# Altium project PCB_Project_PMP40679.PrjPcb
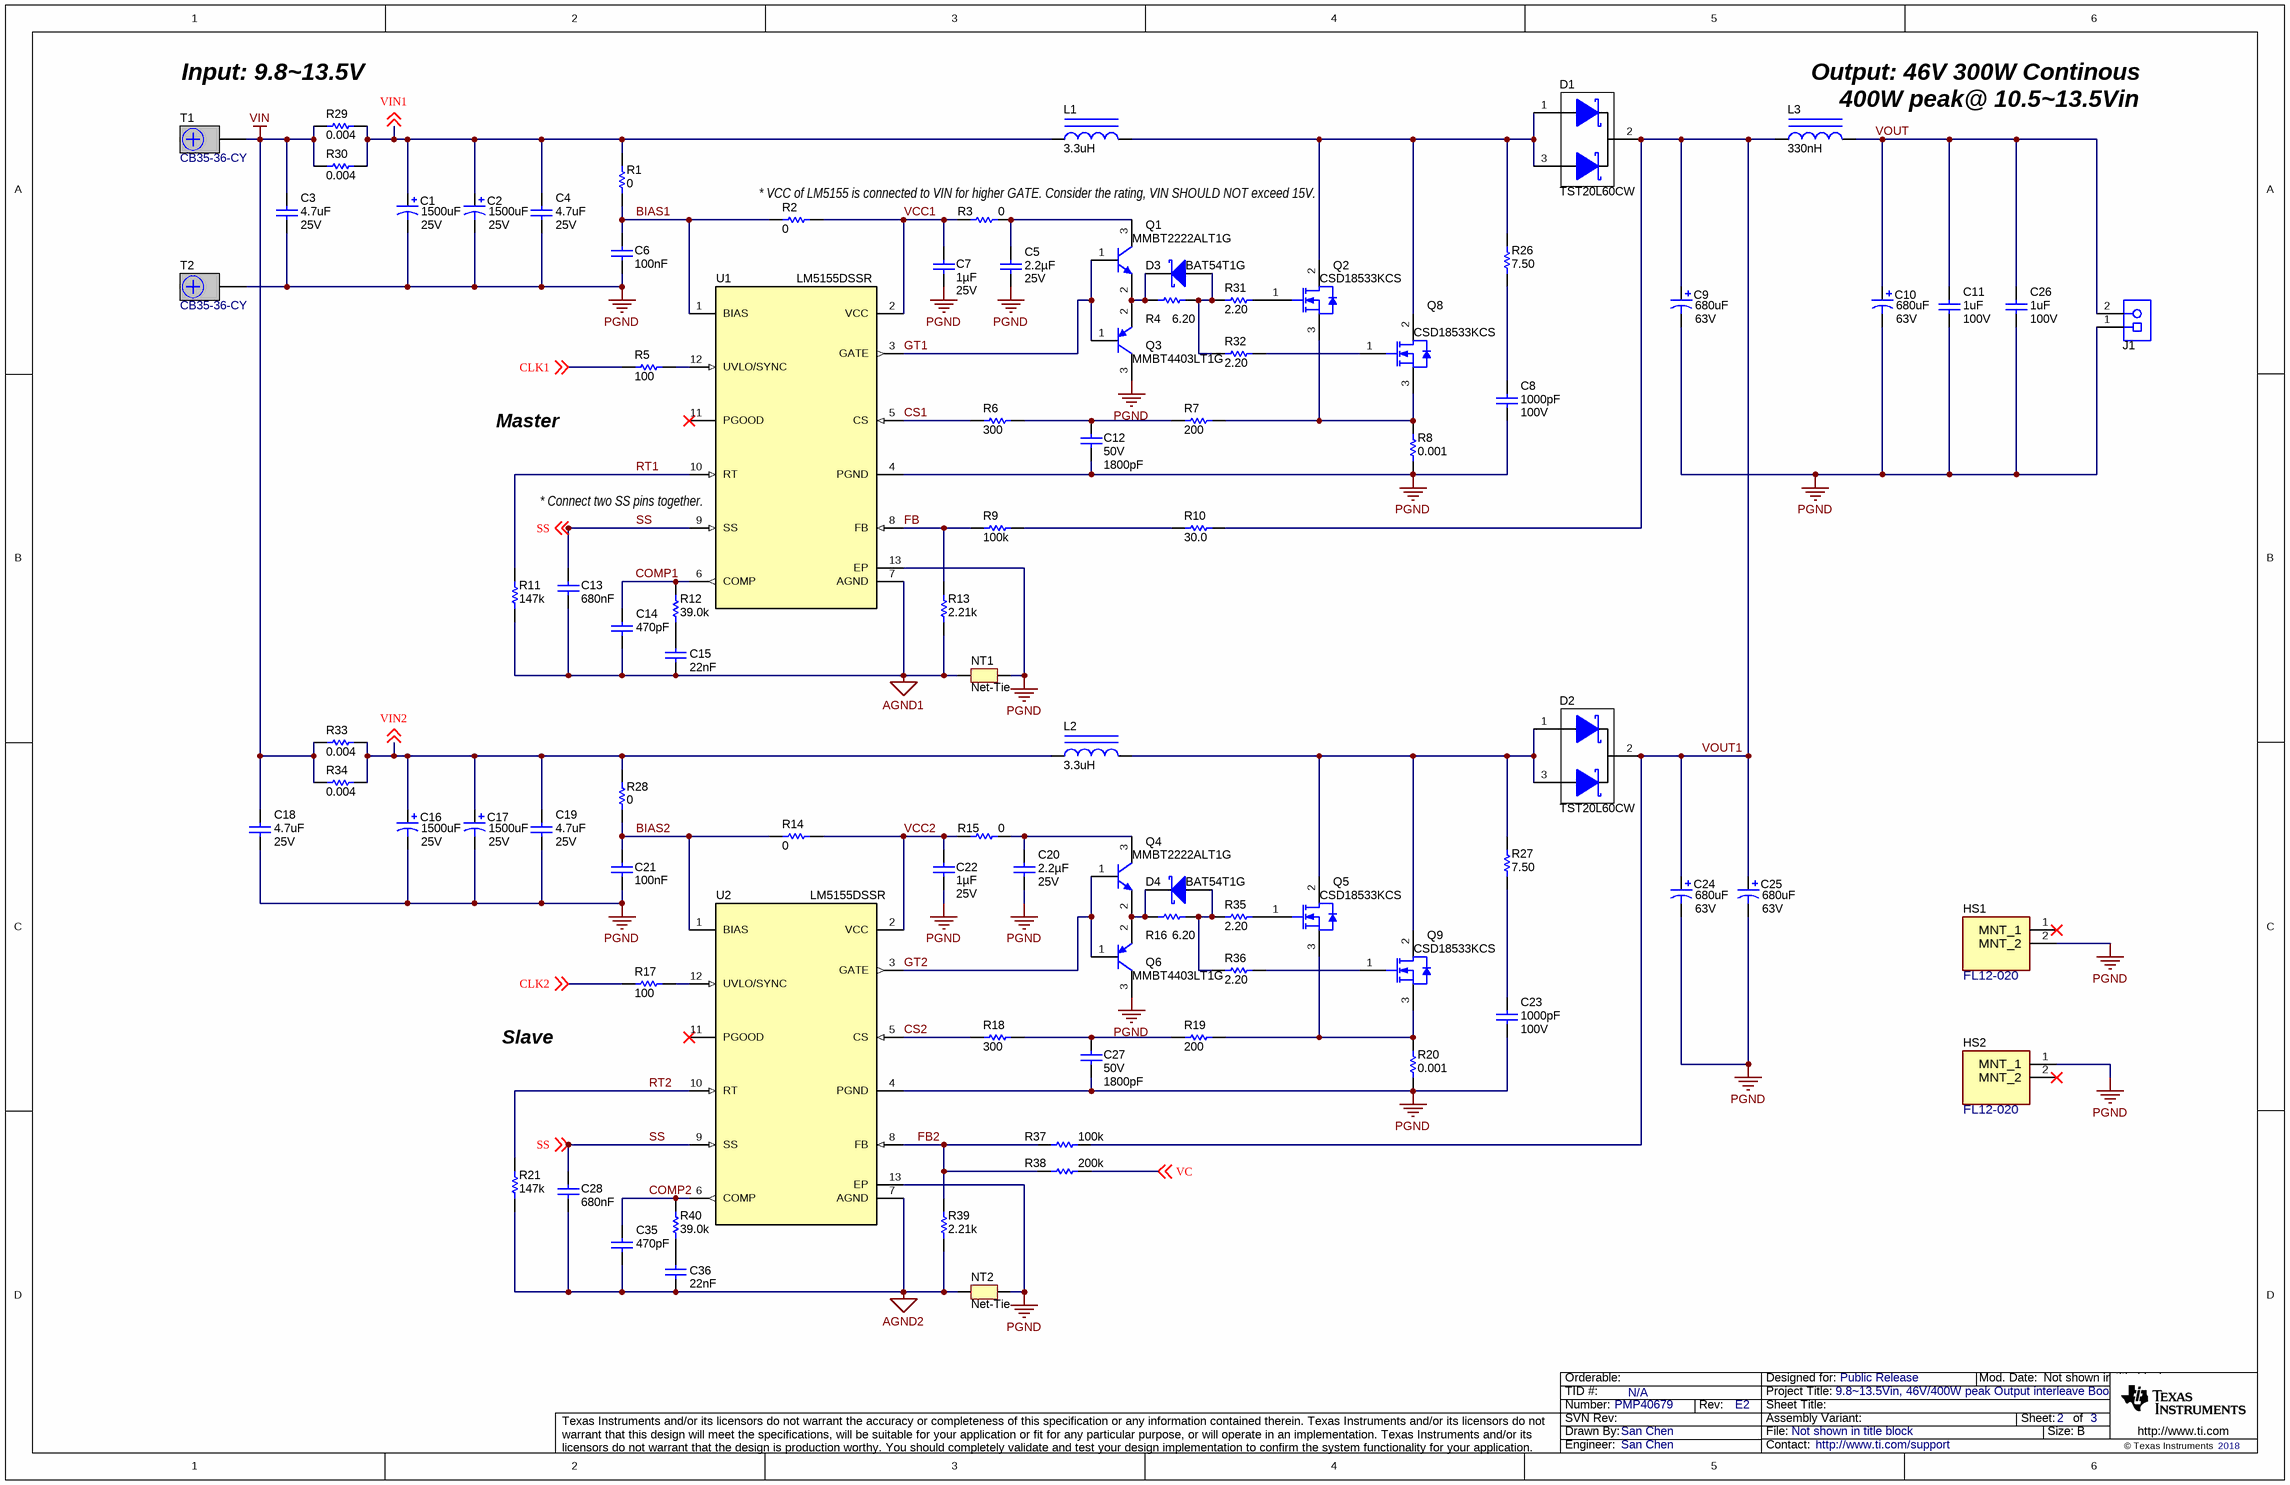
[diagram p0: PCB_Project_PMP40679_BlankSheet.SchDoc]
CopyrightYear: 2018; PCB_Layout: San Chen; PCB_Rev: E2; PRJ_Customer: Public Release; PRJ_Engineer: San Chen; PRJ_Number: PMP40679; PRJ_Title: 9.8~13.5Vin, 46V/400W peak Output interleave Boost; SCH_Rev: E2; TechSupport: http://www.ti.com/support; TID: N/A
3 sheets, 114 parts. Net scope: global (net labels, ports and power ports of the same name join across sheets).
Board file: PCB_Project_PMP40679_PCB.PcbDoc
Sheets:
  PCB_Project_PMP40679_BlankSheet.SchDoc
  PCB_Project_PMP40679_CoverSheet.SchDoc
  PCB_Project_PMP40679_EVM_Hardware.SchDoc

## Sheet PCB_Project_PMP40679_BlankSheet.SchDoc
size 431 x 279 mm; Date: Not shown in title block; ApprovedBy: Not shown in title block; CheckedBy: Not shown in title block; Author: Not shown in title block; CompanyName: Not shown in title block; DrawnBy: San Chen; Engineer: Not shown in title block; Organization: Not shown in title block; Address1: Not shown in title block; Address2: Not shown in title block; Address3: Not shown in title block; Address4: Not shown in title block; DocumentNumber: 1; Revision: Use project parameter SCH_Rev; SheetNumber: 2; SheetTotal: 3; PageSetup: Record=PageOptions¦CenterHorizontal=True¦CenterVertical=True¦PrintScale=1.00¦XCorrection=1.00¦YCorrection=1.00¦PrintKind=0¦BorderSize=5000000¦LeftOffset=0¦BottomOffset=0¦Orientation=2¦PaperLength=1000¦PaperWidth=1000¦Scale=100¦PaperSource=15¦PrintQuality=600¦MediaType=1¦DitherType=10¦PaperKind=Letter¦PrintScaleMode=1

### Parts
C1  VDC_V: 25V  ValueDisplayed: 1500uF  [Chemi-Con_1250x2500]  (hidden comment: EKY-250ELL152MK25S)
C2  VDC_V: 25V  ValueDisplayed: 1500uF  [Chemi-Con_1250x2500]  (hidden comment: EKY-250ELL152MK25S)
C3  VDC_V: 25V  ValueDisplayed: 4.7uF  [1206L]  (hidden comment: C3216X7R1E475K085AB)
C4  VDC_V: 25V  ValueDisplayed: 4.7uF  [1206L]  (hidden comment: C3216X7R1E475K085AB)
C5  Cap_F: 2.2µF  VDC_V: 25V  [0805_150]  (hidden comment: 08053C225KAT2A)
C6  Cap_F: 100nF  [0603]  (hidden comment: C0603C104K5RACTU)
C7  Cap_F: 1µF  VDC_V: 25V  [0603]  (hidden comment: C1608X7R1E105K080AB)
C8  VDC_V: 100V  ValueDisplayed: 1000pF  [0805_HV]  (hidden comment: GRM2165C2A102JA01D)
C9  VDC_V: 63V  ValueDisplayed: 680uF  [KY_1600x2500]  (hidden comment: EKY-630ELL681ML25S)
C10  VDC_V: 63V  ValueDisplayed: 680uF  [KY_1600x2500]  (hidden comment: EKY-630ELL681ML25S)
C11  VDC_V: 100V  ValueDisplayed: 1uF  [1206_180]  (hidden comment: C3216X7R2A105K160AA)
C12  VDC_V: 50V  ValueDisplayed: 1800pF  [0603]  (hidden comment: GRM1885C1H182JA01D)
C13  Cap_F: 680nF  [0603]  (hidden comment: GRM188R71A684KA61D)
C14  ValueDisplayed: 470pF  [0603]  (hidden comment: GRM1885C1H471JA01D)
C15  Cap_F: 22nF  [0603]  (hidden comment: C0603C223K3RACTU)
C16  VDC_V: 25V  ValueDisplayed: 1500uF  [Chemi-Con_1250x2500]  (hidden comment: EKY-250ELL152MK25S)
C17  VDC_V: 25V  ValueDisplayed: 1500uF  [Chemi-Con_1250x2500]  (hidden comment: EKY-250ELL152MK25S)
C18  VDC_V: 25V  ValueDisplayed: 4.7uF  [1206L]  (hidden comment: C3216X7R1E475K085AB)
C19  VDC_V: 25V  ValueDisplayed: 4.7uF  [1206L]  (hidden comment: C3216X7R1E475K085AB)
C20  Cap_F: 2.2µF  VDC_V: 25V  [0805_150]  (hidden comment: 08053C225KAT2A)
C21  Cap_F: 100nF  [0603]  (hidden comment: C0603C104K5RACTU)
C22  Cap_F: 1µF  VDC_V: 25V  [0603]  (hidden comment: C1608X7R1E105K080AB)
C23  VDC_V: 100V  ValueDisplayed: 1000pF  [0805_HV]  (hidden comment: GRM2165C2A102JA01D)
C24  VDC_V: 63V  ValueDisplayed: 680uF  [KY_1600x2500]  (hidden comment: EKY-630ELL681ML25S)
C25  VDC_V: 63V  ValueDisplayed: 680uF  [KY_1600x2500]  (hidden comment: EKY-630ELL681ML25S)
C26  VDC_V: 100V  ValueDisplayed: 1uF  [1206_180]  (hidden comment: C3216X7R2A105K160AA)
C27  VDC_V: 50V  ValueDisplayed: 1800pF  [0603]  (hidden comment: GRM1885C1H182JA01D)
C28  Cap_F: 680nF  [0603]  (hidden comment: GRM188R71A684KA61D)
C35  ValueDisplayed: 470pF  [0603]  (hidden comment: GRM1885C1H471JA01D)
C36  Cap_F: 22nF  [0603]  (hidden comment: C0603C223K3RACTU)
D1  TST20L60CW  [TO-220AB]
D2  TST20L60CW  [TO-220AB]
D3  BAT54T1G  [SOD-123]
D4  BAT54T1G  [SOD-123]
HS1  FL12-020  [PCBComponent_1]
HS2  FL12-020  [PCBComponent_1]
J1  1715721  [PhoenixContact_1715721]  (value not drawn)
L1  ValueDisplayed: 3.3uH  [SER2915L]  (hidden comment: SER2915L-332KL)
L2  ValueDisplayed: 3.3uH  [SER2915L]  (hidden comment: SER2915L-332KL)
L3  ValueDisplayed: 330nH  [WE-HCI_5040]  (hidden comment: 744316033)
NT1  Net-Tie  [Net-Tie_10mil]  (net tie, no BOM)
NT2  Net-Tie  [Net-Tie_10mil]  (net tie, no BOM)
Q1  MMBT2222ALT1G  [SOT-23]
Q2  CSD18533KCS  [KCS0003B]
Q3  MMBT4403LT1G  [SOT-23]
Q4  MMBT2222ALT1G  [SOT-23]
Q5  CSD18533KCS  [KCS0003B]
Q6  MMBT4403LT1G  [SOT-23]
Q8  CSD18533KCS  [KCS0003B]
Q9  CSD18533KCS  [KCS0003B]
R1  ValueDisplayed: 0  [0603]  (hidden comment: RC0603JR-070RL)
R2  ValueDisplayed: 0  [0603]  (hidden comment: RC0603JR-070RL)
R3  ValueDisplayed: 0  [0603]  (hidden comment: RC0603JR-070RL)
R4  ValueDisplayed: 6.20  [0805_HV]  (hidden comment: RC0805FR-076R2L)
R5  ValueDisplayed: 100  [0603]  (hidden comment: RC0603FR-07100RL)
R6  ValueDisplayed: 300  [0603]  (hidden comment: RC0603FR-07300RL)
R7  ValueDisplayed: 200  [0603]  (hidden comment: RC0603FR-07200RL)
R8  ValueDisplayed: 0.001  [2512]  (hidden comment: ERJ-M1WTF1M0U)
R9  ValueDisplayed: 100k  [0603]  (hidden comment: RC0603FR-07100KL)
R10  ValueDisplayed: 30.0  [0603]  (hidden comment: RC0603FR-0730RL)
R11  ValueDisplayed: 147k  [0603]  (hidden comment: RC0603FR-07147KL)
R12  ValueDisplayed: 39.0k  [0603]  (hidden comment: RC0603FR-0739KL)
R13  ValueDisplayed: 2.21k  [0603]  (hidden comment: RC0603FR-072K21L)
R14  ValueDisplayed: 0  [0603]  (hidden comment: RC0603JR-070RL)
R15  ValueDisplayed: 0  [0603]  (hidden comment: RC0603JR-070RL)
R16  ValueDisplayed: 6.20  [0805_HV]  (hidden comment: RC0805FR-076R2L)
R17  ValueDisplayed: 100  [0603]  (hidden comment: RC0603FR-07100RL)
R18  ValueDisplayed: 300  [0603]  (hidden comment: RC0603FR-07300RL)
R19  ValueDisplayed: 200  [0603]  (hidden comment: RC0603FR-07200RL)
R20  ValueDisplayed: 0.001  [2512]  (hidden comment: ERJ-M1WTF1M0U)
R21  ValueDisplayed: 147k  [0603]  (hidden comment: RC0603FR-07147KL)
R26  ValueDisplayed: 7.50  [2512]  (hidden comment: CRCW25127R50FKEG)
R27  ValueDisplayed: 7.50  [2512]  (hidden comment: CRCW25127R50FKEG)
R28  ValueDisplayed: 0  [0603]  (hidden comment: RC0603JR-070RL)
R29  ValueDisplayed: 0.004  [2512]  (hidden comment: ERJ-M1WTF4M0U)
R30  ValueDisplayed: 0.004  [2512]  (hidden comment: ERJ-M1WTF4M0U)
R31  ValueDisplayed: 2.20  [0805_HV]  (hidden comment: RC0805FR-072R2L)
R32  ValueDisplayed: 2.20  [0805_HV]  (hidden comment: RC0805FR-072R2L)
R33  ValueDisplayed: 0.004  [2512]  (hidden comment: ERJ-M1WTF4M0U)
R34  ValueDisplayed: 0.004  [2512]  (hidden comment: ERJ-M1WTF4M0U)
R35  ValueDisplayed: 2.20  [0805_HV]  (hidden comment: RC0805FR-072R2L)
R36  ValueDisplayed: 2.20  [0805_HV]  (hidden comment: RC0805FR-072R2L)
R37  ValueDisplayed: 100k  [0603]  (hidden comment: RC0603FR-07100KL)
R38  ValueDisplayed: 200k  [0603]  (hidden comment: RC0603FR-07200KL)
R39  ValueDisplayed: 2.21k  [0603]  (hidden comment: RC0603FR-072K21L)
R40  ValueDisplayed: 39.0k  [0603]  (hidden comment: RC0603FR-0739KL)
T1  CB35-36-CY  [CB35-36-CY]
T2  CB35-36-CY  [CB35-36-CY]
U1  LM5155DSSR  [DSS0012B]
U2  LM5155DSSR  [DSS0012B]

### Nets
AGND1: C13.2 C14.2 C15.2 NT1.2 R11.1 R13.1 U1.7(AGND)
AGND2: C28.2 C35.2 C36.2 NT2.2 R21.1 R39.1 U2.7(AGND)
PGND: C1.2(-) C2.2(-) C3.2 C4.2 C5.2 C6.2 C7.2 C8.2 C9.2(-) C10.2(-) C11.2 C12.2 C16.2(-) C17.2(-) C18.2 C19.2 C20.2 C21.2 C22.2 C23.2 C24.2(-) C25.2(-) C26.2 C27.2 HS1.2(MNT_2) HS2.1(MNT_1) J1.1 NT1.1 NT2.1 Q3.3(C) Q6.3(C) R8.1 R20.1 T2.1 U1.4(PGND) U1.13(EP) U2.4(PGND) U2.13(EP)
VIN: C3.1 C18.1 R29.1 R30.1 R33.1 R34.1 T1.1
BIAS1: C6.1 R1.1 R2.2 U1.1(BIAS)
BIAS2: C21.1 R14.2 R28.1 U2.1(BIAS)
CLK1: R5.1 ; off-sheet CLK1
CLK2: R17.1 ; off-sheet CLK2
COMP1: C14.1 R12.2 U1.6(COMP)
COMP2: C35.1 R40.2 U2.6(COMP)
CS1: R6.1 U1.5(CS)
CS2: R18.1 U2.5(CS)
FB: R9.1 R13.2 U1.8(FB)
FB2: R37.1 R38.1 R39.2 U2.8(FB)
GT1: Q1.1(B) Q3.1(B) U1.3(GATE)
GT2: Q4.1(B) Q6.1(B) U2.3(GATE)
RT1: R11.2 U1.10(RT)
RT2: R21.2 U2.10(RT)
SS: C13.1 C28.1 U1.9(SS) U2.9(SS) ; off-sheet SS
VC: R38.2 ; off-sheet VC
VCC1: C7.1 R2.1 R3.2 U1.2(VCC)
VCC2: C22.1 R14.1 R15.2 U2.2(VCC)
VIN1: C1.1(+) C2.1(+) C4.1 L1.1 R1.2 R29.2 R30.2 ; off-sheet VIN1
VIN2: C16.1(+) C17.1(+) C19.1 L2.2 R28.2 R33.2 R34.2 ; off-sheet VIN2
VOUT: C10.1(+) C11.1 C26.1 J1.2 L3.2
VOUT1: C9.1(+) C24.1(+) C25.1(+) D1.2(K) D2.2(K) L3.1 R10.2 R37.2
NetC5_1: C5.1 Q1.3(C) R3.1
NetC8_1: C8.1 R26.1
NetC12_1: C12.1 R6.2 R7.1
NetC15_1: C15.1 R12.1
NetC20_1: C20.1 Q4.3(C) R15.1
NetC23_1: C23.1 R27.1
NetC27_1: C27.1 R18.2 R19.1
NetC36_1: C36.1 R40.1
NetD1_1: D1.1(A) D1.3(A) L1.2 Q2.2(D) Q8.2(D) R26.2
NetD2_1: D2.1(A) D2.3(A) L2.1 Q5.2(D) Q9.2(D) R27.2
NetD3_1: D3.1(K) Q1.2(E) Q3.2(E) R4.1
NetD3_2: D3.2(A) R4.2 R31.1 R32.1
NetD4_1: D4.1(K) Q4.2(E) Q6.2(E) R16.1
NetD4_2: D4.2(A) R16.2 R35.1 R36.1
NetQ2_1: Q2.1(G) R31.2
NetQ2_3: Q2.3(S) Q8.3(S) R7.2 R8.2
NetQ5_1: Q5.1(G) R35.2
NetQ5_3: Q5.3(S) Q9.3(S) R19.2 R20.2
NetQ8_1: Q8.1(G) R32.2
NetQ9_1: Q9.1(G) R36.2
NetR5_2: R5.2 U1.12(UVLO/SYNC)
NetR9_2: R9.2 R10.1
NetR17_2: R17.2 U2.12(UVLO/SYNC)

Not connected (* = marked no-connect by the designer): HS1 1(MNT_1)*; HS2 2(MNT_2)*; U1 11(PGOOD)*; U2 11(PGOOD)*

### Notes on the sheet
- Input: 9.8
  3.5V
- Output: 46V 300W Continous
- (near L3) 400W peak@ 10.5
  3.5Vin
- * VCC of LM5155 is connected to VIN for higher GATE. Consider the rating, VIN SHOULD NOT exceed 15V.
- Master
- (near U1) * Connect two SS pins together.
- Slave

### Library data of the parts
C1 C2 C16 C17 = CMP-0010401-1: CAP, AL, 1500 uF, 25 V, +/- 20%, TH; Manufacturer: Chemi-Con; TaMin_C: -40°C; Polarized: Y; SizeAreaWB_mm2: 210.25; Value1: Unknown; U/M: EA; Value: 1500uF; TaMax_C: 105°C; SizeZ_mm: 26.5; SizeX_mm: 12.5; Cap_Case: 12.5x25; SizeArea_mm2: 156.25; CompType: Capacitor; AEC Qualified: N; Cap_F: 1.5mF; IRMS_A: 2.23A; AEC Category: Q200
C3 C4 C18 C19 = CMP-0008693-2: CAP, CERM, 4.7 uF, 25 V, +/- 10%, X7R, 1206; Manufacturer: TDK; TaMin_C: -55°C; Polarized: N; SizeAreaWB_mm2: 10.92; Value1: Unknown; U/M: EA; Value: 4.7uF; TaMax_C: 125°C; SizeZ_mm: 1.35; SizeX_mm: 3.2; SizeY_mm: 1.6; Cap_Case: 1206; SizeArea_mm2: 5.12; CompType: Capacitor; Cap_F: 4.7µF; AEC Category: Q200
C5 C20 = CMP-0007573-2: CAP, CERM, 2.2 uF, 25 V, +/- 10%, X7R, 0805; Manufacturer: AVX; TaMin_C: -55°C; Polarized: N; SizeAreaWB_mm2: 6.75; Value1: Unknown; U/M: EA; Value: 2.2uF; TaMax_C: 125°C; SizeZ_mm: 1.5; SizeX_mm: 2; SizeY_mm: 1.25; Cap_Case: 0805; SizeArea_mm2: 2.5; AEC Category: Q200
C6 C21 = CMP-0006861-4: CAP, CERM, 0.1 uF, 50 V, +/- 10%, X7R, 0603; Manufacturer: Kemet; TaMin_C: -55°C; Polarized: N; SizeAreaWB_mm2: 4.68; Value1: Unknown; U/M: EA; Value: 0.1uF; TaMax_C: 125°C; SizeZ_mm: 1; SizeX_mm: 1.6; SizeY_mm: 0.8; Value2: 50V; SizeArea_mm2: 1.28; CompType: Capacitor; AEC Category: Q200
C7 C22 = CMP-0007040-4: CAP, CERM, 1 uF, 25 V, +/- 10%, X7R, 0603; Manufacturer: TDK; TaMin_C: -55°C; Polarized: N; SizeAreaWB_mm2: 4.68; Value1: Unknown; U/M: EA; Value: 1uF; TaMax_C: 125°C; SizeZ_mm: 1; SizeX_mm: 1.6; SizeY_mm: 0.8; SizeArea_mm2: 1.28; AEC Category: Q200
C8 C23 = CMP-0008094-2: CAP, CERM, 1000 pF, 100 V, +/- 5%, C0G/NP0, 0805; Manufacturer: MuRata; TaMin_C: -55°C; Polarized: N; SizeAreaWB_mm2: 6.75; Value1: Unknown; U/M: EA; Value: 1000pF; TaMax_C: 125°C; SizeZ_mm: 1.45; SizeX_mm: 2; SizeY_mm: 1.25; Cap_Case: 0805; SizeArea_mm2: 2.5; Cap_F: 1nF; AEC Category: Q200
C9 C10 C24 C25 = CMP-0009872-2: CAP, AL, 680 uF, 63 V, +/- 20%, 0.025 ohm, TH; Manufacturer: Chemi-Con; TaMin_C: -40°C; ESR_ohm: 0.025; Polarized: Y; SizeAreaWB_mm2: 324; U/M: EA; Value: 680uF; TaMax_C: 105°C; SizeZ_mm: 26.5; SizeX_mm: 16; Cap_Case: 16x25mm; SizeArea_mm2: 256; CompType: Capacitor; AEC Qualified: N; Cap_F: 680µF; IRMS_A: 2.6A; AEC Category: Q200
C11 C26 = CMP-0008710-2: CAP, CERM, 1 uF, 100 V, +/- 10%, X7R, 1206; Manufacturer: TDK; TaMin_C: -55°C; ESR_ohm: 4.575m; Polarized: N; SizeAreaWB_mm2: 10.92; Value1: 0.004575 ohm; U/M: EA; Value: 1uF; TaMax_C: 125°C; SizeZ_mm: 1.8; SizeX_mm: 3.2; SizeY_mm: 1.6; SizeArea_mm2: 5.12; Cap_F: 1µF; IRMS_A: 3.39639A; AEC Category: Q200
C12 C27 = CMP-0007192-4: CAP, CERM, 1800 pF, 50 V, +/- 5%, C0G/NP0, 0603; Manufacturer: MuRata; TaMin_C: -55°C; Polarized: N; SizeAreaWB_mm2: 4.68; Value1: Unknown; U/M: EA; Value: 1800pF; TaMax_C: 125°C; SizeZ_mm: 1; SizeX_mm: 1.6; SizeY_mm: 0.8; SizeArea_mm2: 1.28; Cap_F: 1.8nF; AEC Category: Q200
C13 C28 = CMP-0007375-4: CAP, CERM, 0.68 uF, 10 V, +/- 10%, X7R, 0603; Manufacturer: MuRata; TaMin_C: -55°C; Polarized: N; SizeAreaWB_mm2: 4.68; Value1: Unknown; U/M: EA; Value: 0.68uF; TaMax_C: 125°C; SizeZ_mm: 1; SizeX_mm: 1.6; SizeY_mm: 0.8; Value2: 10V; SizeArea_mm2: 1.28; CompType: Capacitor; AEC Category: Q200
C14 C35 = CMP-0007221-4: CAP, CERM, 470 pF, 50 V, +/- 5%, C0G/NP0, 0603; Manufacturer: MuRata; TaMin_C: -55°C; Polarized: N; SizeAreaWB_mm2: 4.68; Value1: Unknown; U/M: EA; Value: 470pF; TaMax_C: 125°C; SizeZ_mm: 1; SizeX_mm: 1.6; SizeY_mm: 0.8; Value2: 50V; SizeArea_mm2: 1.28; CompType: Capacitor; AEC Category: Q200
C15 C36 = CMP-0006899-4: CAP, CERM, 0.022 uF, 25 V, +/- 10%, X7R, 0603; Manufacturer: Kemet; TaMin_C: -55°C; Polarized: N; SizeAreaWB_mm2: 4.68; Value1: Unknown; U/M: EA; TaMax_C: 125°C; SizeZ_mm: 1; SizeX_mm: 1.6; SizeY_mm: 0.8; Value2: 25V; SizeArea_mm2: 1.28; CompType: Capacitor; AEC Category: Q200
D1 D2 = CMP-0028764-3: Diode, Schottky, 60 V, 20 A, TH; Manufacturer: Taiwan Semiconductor; PartNumber: TST20L60CWC0G; Vf: 0.65V; VRRM: 60V; IF: 20A
D3 D4 = CMP-0028457-2: Diode, Schottky, 30 V, 0.2 A, SOD-123; Manufacturer: ON Semiconductor; SizeArea_mm2: 6.545; Io_A: 2dA; SizeX_mm: 3.85; Value1: 0.2A; SizeY_mm: 1.7; AEC Category: Q101; Vf_V: 8dV; TJmax_C: 125°C; Green_Lifecycle: Not Set; RJC_CperW: 174; Value: 30V; Value2: 0.8V; SizeAreaWB_mm2: 13.095; Green_REACh: Incomplete; SizeZ_mm: 1.35
HS1 HS2 = CMP-0087085-1: HEATSINK FOR 3 TO-220; Manufacturer: FL Heatsink
J1 = CMP-0055471-1: Terminal Block, 5.08 mm, 2x1, TH; Manufacturer: Phoenix Contact; Cert_VDE: Y; CNHeader: FALSE; Current_A: 17.5A; Green_Lifecycle: Not Set; Gender: Female; Cert_CULUS: N; Green_REACh: Incomplete; Voltage_V: 400V; Row_Count: 1; Pitch_mm: 5.08; ContactFinish: Tin; CT: TRUE
L1 L2 = CMP-0060859-1: Inductor, Shielded E Core, Ferrite, 3.3 uH, 30 A, 0.0015 ohm, SMD; Manufacturer: Coilcraft; Isat: 57A @ 30% inductance drop; Irms: 30A @ 40C rise; Green_Lifecycle: Not Set; DCR_ohm: 1.5m; Green_REACh: Incomplete; SizeAreaWB_mm2: 651.82; Value: 3.3uH; Imax_A: 30A; SizeZ_mm: 15.36; SizeX_mm: 27.9; SizeY_mm: 19.8; SizeArea_mm2: 552.42; Ind_H: 3.3µH; AEC Category: Q200
L3 = CMP-0063948-1: Inductor, Wirewound, 330 nH, 18.5 A, 0.00175 ohm, SMD; Manufacturer: Wurth Elektronik; Isat: 20A @ 30% inductance drop; Irms: 18.5A @ 50C rise; Green_Lifecycle: Active; SizeAreaWB_mm2: 55.48; DCR_ohm: 1.75m; Green_REACh: Passed; Value: 330nH; Imax_A: 18.5A; SizeZ_mm: 4.3; SizeX_mm: 5.6; SizeY_mm: 5.3; SizeArea_mm2: 29.68; AEC Qualified: N; AEC Category: Q200
NT1 NT2 = Net-Tie: Single point connection between nets.; SymbolCreator: codlsc
Q1 Q4 = CMP-0000461-2: Transistor, NPN, 40 V, 0.6 A, SOT-23; Manufacturer: ON Semiconductor; TaMax_C: 150°C; Value1: 0.6 A; Vcesat1_V: 1V; SizeX_mm: 2.5; SizeY_mm: 3; TaMin_C: -55°C; IcRated_A: 6dA; CompType: BJT; SizeZ_mm: 1.1; Value: 40 V; SizeArea_mm2: 7.5; NPN: 1; Vceo_V: 40V; PNP: 0; AEC Category: Q101; SizeAreaWB_mm2: 14; U/M: EA
Q2 Q5 Q8 Q9 = CMP-0000814-1: MOSFET, N-CH, 60 V, 100 A, KCS0003B (TO-220-3); Alternate Manufacturer: None; Manufacturer: Texas Instruments; SizeZ_mm: 20.45; ChType: N; Value2: 28 nC; Value1: 0; VdsMax_V: 60V; SizeX_mm: 4.55; SizeY_mm: 10.16; Vgs_V: 20V; Value: 60V; Rdson45_ohm: 9m; SizeArea_mm2: 46.228; AEC Category: Q101; IdsMax_A: 100A; SizeAreaWB_mm2: 79.648; U/M: EA; QgTyp_nC: 28
Q3 Q6 = CMP-0000327-2: Transistor, PNP, 40 V, 0.6 A, SOT-23; Manufacturer: Fairchild Semiconductor; TaMax_C: 150°C; Value2: 500; Value1: 0.6 A; Vcesat1_V: 7.5dV; SizeX_mm: 2.5; SizeY_mm: 3; TaMin_C: -55°C; IcRated_A: 6dA; CompType: BJT; SizeZ_mm: 1.1; Value: 40 V; SizeArea_mm2: 7.5; NPN: 0; Vceo_V: 40V; PNP: 1; AEC Category: Q101; SizeAreaWB_mm2: 14; U/M: EA
R1-R3 R14 R15 R28 = CMP-0025885-5: RES, 0, 5%, 0.1 W, 0603; Manufacturer: Yageo; Power_W: 100mW; TempCo: 200 ppm/C; Value_Code: 0000; Value: 0; EIA_Code: E24; SizeX_mm: 1.6; SizeZ_mm: 1; Value2: 0.1W; SizeArea_mm2: 1.28; AEC Qualified: N; VDC_V: 75V; AEC Category: Q200; SizeY_mm: 0.8; SizeAreaWB_mm2: 4.68
R4 R16 = CMP-0021950-2: RES, 6.20, 1%, 0.125 W, 0805; Manufacturer: Yageo America; Power_W: 125mW; TempCo: 200 ppm/C; Value_Code: 6R20; U/M: EA; Value: 6.20; Res_ohm: 6.2; SizeX_mm: 2; SizeY_mm: 1.25; SizeZ_mm: 1.45; Value2: 0.125W; SizeArea_mm2: 2.5; VDC_V: 150V; AEC Category: Q200
R5 R17 = CMP-0022736-4: RES, 100, 1%, 0.1 W, 0603; Manufacturer: Yageo; Power_W: 100mW; TempCo: 100 ppm/C; Value_Code: 100R; Value: 100; EIA_Code: E96; SizeX_mm: 1.6; SizeY_mm: 0.8; SizeZ_mm: 1; Value2: 0.1W; SizeArea_mm2: 1.28; AEC Qualified: N; VDC_V: 75V; AEC Category: Q200; SizeAreaWB_mm2: 4.68
R6 R18 = CMP-0023013-5: RES, 300, 1%, 0.1 W, 0603; Manufacturer: Yageo; Power_W: 100mW; TempCo: 100 ppm/C; Value_Code: 300R; Value: 300; SizeX_mm: 1.6; SizeY_mm: 0.8; SizeZ_mm: 1; Value2: 0.1W; SizeArea_mm2: 1.28; AEC Qualified: N; VDC_V: 75V; AEC Category: Q200; SizeAreaWB_mm2: 4.68
R7 R19 = CMP-0022902-5: RES, 200, 1%, 0.1 W, 0603; Manufacturer: Yageo; Power_W: 100mW; TempCo: 100 ppm/C; Value_Code: 200R; Value: 200; EIA_Code: E96; SizeX_mm: 1.6; SizeY_mm: 0.8; SizeZ_mm: 1; Value2: 0.1W; SizeArea_mm2: 1.28; AEC Qualified: N; VDC_V: 75V; AEC Category: Q200; SizeAreaWB_mm2: 4.68
R8 R20 = CMP-0015817-2: RES, 0.001, 1%, 1 W, 2512; Manufacturer: Panasonic; Power_W: 1W; TempCo: ppm/C; Value_Code: 1L000; U/M: EA; Value: 0.001; EIA_Code: E96; Res_ohm: 1m; SizeX_mm: 6.3; SizeY_mm: 3.2; SizeZ_mm: 0.71; SizeArea_mm2: 20.16; AEC Category: Q200
R9 R37 = CMP-0022735-5: RES, 100 k, 1%, 0.1 W, 0603; Manufacturer: Yageo; Power_W: 100mW; TempCo: 100 ppm/C; Value: 100k; EIA_Code: E96; SizeX_mm: 1.6; SizeY_mm: 0.8; SizeZ_mm: 1; Value2: 0.1W; SizeArea_mm2: 1.28; AEC Qualified: N; VDC_V: 75V; AEC Category: Q200; SizeAreaWB_mm2: 4.68
R10 = CMP-0023023-4: RES, 30.0, 1%, 0.1 W, 0603; Manufacturer: Yageo; Power_W: 100mW; TempCo: 100 ppm/C; Value_Code: 30R0; Value: 30.0; Res_ohm: 30; SizeX_mm: 1.6; SizeY_mm: 0.8; SizeZ_mm: 1; Value2: 0.1W; SizeArea_mm2: 1.28; AEC Qualified: N; VDC_V: 75V; AEC Category: Q200; SizeAreaWB_mm2: 4.68
R11 R21 = CMP-0022800-4: RES, 147 k, 1%, 0.1 W, 0603; Manufacturer: Yageo; Power_W: 100mW; TempCo: 100 ppm/C; Value: 147k; EIA_Code: E96; SizeX_mm: 1.6; SizeY_mm: 0.8; SizeZ_mm: 1; Value2: 0.1W; SizeArea_mm2: 1.28; AEC Qualified: N; VDC_V: 75V; AEC Category: Q200; SizeAreaWB_mm2: 4.68
R12 R40 = CMP-0023073-5: RES, 39.0 k, 1%, 0.1 W, 0603; Manufacturer: Yageo; Power_W: 100mW; TempCo: 100 ppm/C; Value_Code: 39k0; Value: 39.0k; Res_ohm: 39k; SizeX_mm: 1.6; SizeY_mm: 0.8; SizeZ_mm: 1; Value2: 0.1W; SizeArea_mm2: 1.28; AEC Qualified: N; VDC_V: 75V; AEC Category: Q200; SizeAreaWB_mm2: 4.68
R13 R39 = CMP-0022984-5: RES, 2.21 k, 1%, 0.1 W, 0603; Manufacturer: Yageo; Power_W: 100mW; TempCo: 100 ppm/C; Value_Code: 2k21; Value: 2.21k; EIA_Code: E96; SizeX_mm: 1.6; SizeY_mm: 0.8; SizeZ_mm: 1; Value2: 0.1W; SizeArea_mm2: 1.28; AEC Qualified: N; VDC_V: 75V; AEC Category: Q200; SizeAreaWB_mm2: 4.68
R26 R27 = CMP-0015723-3: RES, 7.50, 1%, 1 W, AEC-Q200 Grade 0, 2512; Manufacturer: Vishay-Dale; Power_W: 1W; TempCo: 100 ppm/C; Value_Code: 7R50; Value: 7.50; EIA_Code: E96; Res_ohm: 7.5; SizeX_mm: 6.3; SizeY_mm: 3.2; SizeZ_mm: 0.71; SizeArea_mm2: 20.16; AEC Qualified: Y; VDC_V: 500V; AEC Grade: 0; AEC Category: Q200
R29 R30 R33 R34 = CMP-0015821-2: RES, 0.004, 1%, 1 W, 2512; Manufacturer: Panasonic; Power_W: 1W; TempCo: ppm/C; Value_Code: 4L000; U/M: EA; Value: 0.004; Res_ohm: 4m; SizeX_mm: 6.3; SizeY_mm: 3.2; SizeZ_mm: 0.71; SizeArea_mm2: 20.16; AEC Category: Q200
R31 R32 R35 R36 = CMP-0021901-2: RES, 2.20, 1%, 0.125 W, 0805; Manufacturer: Yageo America; Power_W: 125mW; TempCo: 200 ppm/C; Value_Code: 2R20; U/M: EA; Value: 2.20; Res_ohm: 2.2; SizeX_mm: 2; SizeY_mm: 1.25; SizeZ_mm: 1.45; Value2: 0.125W; SizeArea_mm2: 2.5; VDC_V: 150V; AEC Category: Q200
R38 = CMP-0022901-4: RES, 200 k, 1%, 0.1 W, 0603; Manufacturer: Yageo; Power_W: 100mW; TempCo: 100 ppm/C; Value: 200k; EIA_Code: E96; SizeX_mm: 1.6; SizeY_mm: 0.8; SizeZ_mm: 1; Value2: 0.1W; AEC Qualified: N; VDC_V: 75V; AEC Category: Q200; SizeArea_mm2: 1.28; SizeAreaWB_mm2: 4.68
T1 T2 = CMP-0055442-1: Terminal 50A Lug; Manufacturer: Panduit; CNHeader: FALSE; Green_Lifecycle: Not Set; Cert_CULUS: Y; Green_REACh: Incomplete; Voltage_V: 600V; CompType: Screw Terminal; ContactFinish: Copper
U1 U2 = CMP-0085413-1: 2.2-MHz Wide Input Nonsynchronous Boost, Sepic, Flyback Controller, DSS0012B (WSON-12); Alternate Manufacturer: Texas Instruments; Alternate PartNumber: LM5155DSST; SizeAreaWB_mm2: 12; SizeX_mm: 2; SizeZ_mm: 0.8; CompType: IC; SizeArea_mm2: 6; AEC Category: Q200; AEC Qualified: N; SizeY_mm: 3

## Sheet PCB_Project_PMP40679_CoverSheet.SchDoc
size 431 x 279 mm; Date: Not shown in title block; ApprovedBy: Not shown in title block; CheckedBy: Not shown in title block; Author: Not shown in title block; CompanyName: Not shown in title block; Engineer: Not shown in title block; Organization: Not shown in title block; Address1: Not shown in title block; Address2: Not shown in title block; Address3: Not shown in title block; Address4: Not shown in title block; DocumentNumber: 1; Revision: Use project parameter SCH_Rev; SheetNumber: 1; SheetTotal: 3; PageSetup: Record=PageOptions¦CenterHorizontal=True¦CenterVertical=True¦PrintScale=1.00¦XCorrection=1.00¦YCorrection=1.00¦PrintKind=0¦BorderSize=5000000¦LeftOffset=0¦BottomOffset=0¦Orientation=2¦PaperLength=1000¦PaperWidth=1000¦Scale=100¦PaperSource=15¦PrintQuality=600¦MediaType=1¦DitherType=10¦PaperKind=Letter¦PrintScaleMode=1
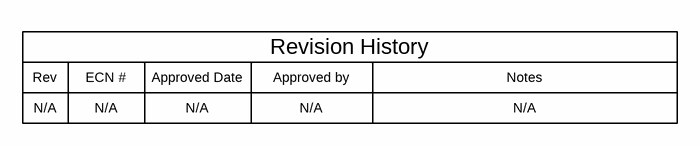
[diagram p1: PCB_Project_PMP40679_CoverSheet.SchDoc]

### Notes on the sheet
- Rev
- N/A
- ECN #
- Approved Date
- Approved by
- Revision History
- Notes

## Sheet PCB_Project_PMP40679_EVM_Hardware.SchDoc
size 431 x 279 mm; Date: Not shown in title block; ApprovedBy: Not shown in title block; CheckedBy: Not shown in title block; Author: Not shown in title block; CompanyName: Not shown in title block; Engineer: Not shown in title block; Organization: Not shown in title block; Address1: Not shown in title block; Address2: Not shown in title block; Address3: Not shown in title block; Address4: Not shown in title block; DocumentNumber: 1; Revision: Use project parameter SCH_Rev; SheetNumber: 3; SheetTotal: 3; PageSetup: Record=PageOptions¦CenterHorizontal=True¦CenterVertical=True¦PrintScale=1.00¦XCorrection=1.00¦YCorrection=1.00¦PrintKind=0¦BorderSize=5000000¦LeftOffset=0¦BottomOffset=0¦Orientation=2¦PaperLength=1000¦PaperWidth=1000¦Scale=100¦PaperSource=15¦PrintQuality=600¦MediaType=1¦DitherType=10¦PaperKind=Letter¦PrintScaleMode=1
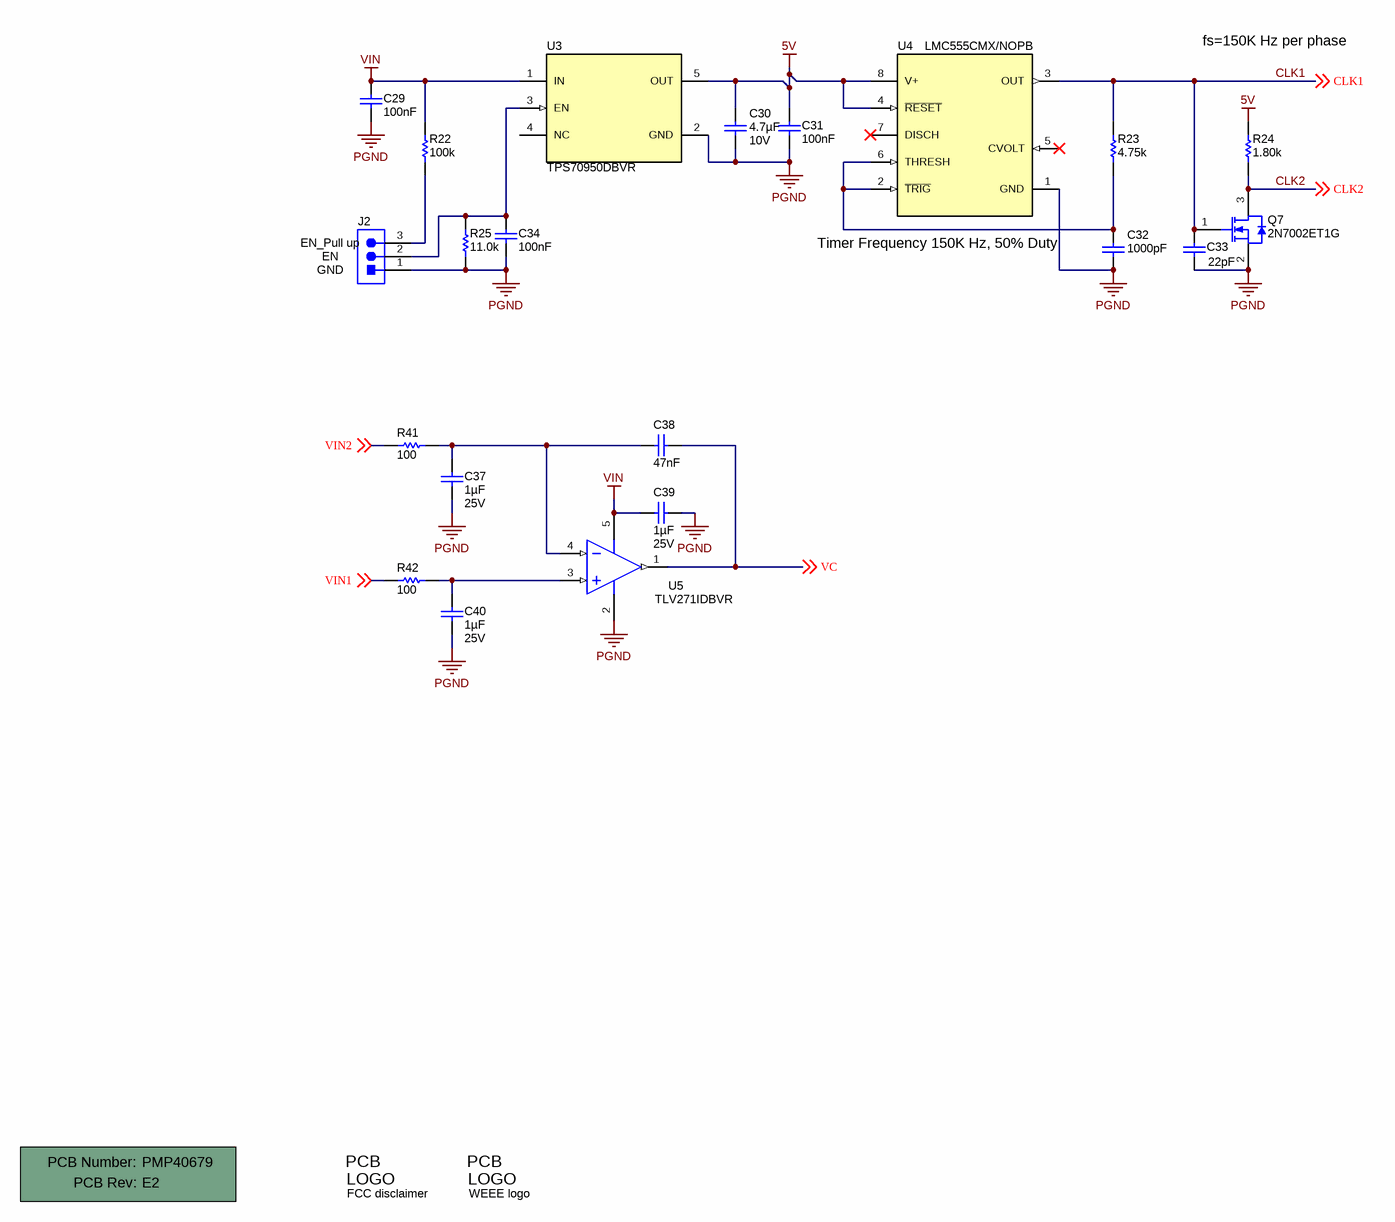
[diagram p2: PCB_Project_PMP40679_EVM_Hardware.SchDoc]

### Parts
!PCB1  Printed Circuit Board  (value not drawn)  (mechanical)
C29  Cap_F: 100nF  [0603]  (hidden comment: C0603C104K5RACTU)
C30  Cap_F: 4.7µF  VDC_V: 10V  [0603]  (hidden comment: GRM188Z71A475ME15D)
C31  Cap_F: 100nF  [0603]  (hidden comment: C0603C104K5RACTU)
C32  ValueDisplayed: 1000pF  [0603]  (hidden comment: GRM1885C1H102FA01J)
C33  ValueDisplayed: 22pF  [0603]  (hidden comment: GRM1885C1H220JA01D)
C34  Cap_F: 100nF  [0603]  (hidden comment: C0603C104K5RACTU)
C37  Cap_F: 1µF  VDC_V: 25V  [0603]  (hidden comment: C1608X7R1E105K080AB)
C38  Cap_F: 47nF  [0603]  (hidden comment: C1608X7R1H473K080AA)
C39  Cap_F: 1µF  VDC_V: 25V  [0603]  (hidden comment: C1608X7R1E105K080AB)
C40  Cap_F: 1µF  VDC_V: 25V  [0603]  (hidden comment: C1608X7R1E105K080AB)
J2  PEC03SAAN  [CONN_PEC03SAAN]  (value not drawn)
Logo1  FCC disclaimer  [FCC_disclaimer]  (no BOM)
Logo2  WEEE logo  [WEEE_Minimum]  (no BOM)
Q7  2N7002ET1G  [SOT-23]
R22  ValueDisplayed: 100k  [0603]  (hidden comment: RC0603FR-07100KL)
R23  ValueDisplayed: 4.75k  [0603]  (hidden comment: RC0603FR-074K75L)
R24  ValueDisplayed: 1.80k  [0603]  (hidden comment: RC0603FR-071K8L)
R25  ValueDisplayed: 11.0k  [0603]  (hidden comment: RC0603FR-0711KL)
R41  ValueDisplayed: 100  [0603]  (hidden comment: RC0603FR-07100RL)
R42  ValueDisplayed: 100  [0603]  (hidden comment: RC0603FR-07100RL)
U3  TPS70950DBVR  [DBV0005A_N]
U4  LMC555CMX/NOPB  [D0008A_N]
U5  TLV271IDBVR  [DBV0005A_N]

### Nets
5V: C30.1 C31.1 R24.2 U3.5(OUT) U4.4(~{RESET}) U4.8(V+)
PGND: C29.2 C30.2 C31.2 C32.2 C33.2 C34.2 C37.2 C39.2 C40.2 J2.1 Q7.2(S) R25.1 U3.2(GND) U4.1(GND) U5.2(GND)
VIN: C29.1 C39.1 R22.2 U3.1(IN) U5.5(VDD)
CLK1: C33.1 Q7.1(G) R23.2 U4.3(OUT) ; off-sheet CLK1
CLK2: Q7.3(D) R24.1 ; off-sheet CLK2
VC: C38.2 U5.1(OUT) ; off-sheet VC
VIN1: R42.1 ; off-sheet VIN1
VIN2: R41.1 ; off-sheet VIN2
NetC32_1: C32.1 R23.1 U4.2(~{TRIG}) U4.6(THRESH)
NetC34_1: C34.1 J2.2 R25.2 U3.3(EN)
NetC37_1: C37.1 C38.1 R41.2 U5.4(IN-)
NetC40_1: C40.1 R42.2 U5.3(IN+)
NetJ2_3: J2.3 R22.1

Not connected (* = marked no-connect by the designer): U3 4(NC); U4 5(CVOLT)* 7(DISCH)*

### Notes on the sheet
- fs=150K Hz per phase
- (near J2) GND
- (near J2) EN
- (near J2) EN_Pull up
- Timer Frequency 150K Hz, 50% Duty

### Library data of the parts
!PCB1 = CMP-0003618-2: Manufacturer: Any; PartNumber: PMP40679
C29 C31 C34 = CMP-0006861-4: as C6 on sheet PCB_Project_PMP40679_BlankSheet
C30 = CMP-0007498-4: CAP, CERM, 4.7 uF, 10 V, +/- 20%, X7R, 0603; Manufacturer: MuRata; TaMin_C: -55°C; Polarized: N; SizeAreaWB_mm2: 4.68; Value1: Unknown; U/M: EA; Value: 4.7uF; TaMax_C: 125°C; SizeZ_mm: 1; SizeX_mm: 1.6; SizeY_mm: 0.8; SizeArea_mm2: 1.28; AEC Category: Q200
C32 = CMP-0007172-4: CAP, CERM, 1000 pF, 50 V, +/- 1%, C0G/NP0, 0603; Manufacturer: MuRata; TaMin_C: -55°C; Polarized: N; SizeAreaWB_mm2: 4.68; Value1: Unknown; U/M: EA; Value: 1000pF; TaMax_C: 125°C; SizeZ_mm: 1; SizeX_mm: 1.6; SizeY_mm: 0.8; Value2: 50V; SizeArea_mm2: 1.28; CompType: Capacitor; Cap_F: 1nF; AEC Category: Q200
C33 = CMP-0007196-4: CAP, CERM, 22 pF, 50 V, +/- 5%, C0G/NP0, 0603; Manufacturer: MuRata; TaMin_C: -55°C; Polarized: N; SizeAreaWB_mm2: 4.68; Value1: Unknown; U/M: EA; Value: 22pF; TaMax_C: 125°C; SizeZ_mm: 1; SizeX_mm: 1.6; SizeY_mm: 0.8; Value2: 50V; SizeArea_mm2: 1.28; CompType: Capacitor; AEC Category: Q200
C37 C39 C40 = CMP-0007040-4: as C7 on sheet PCB_Project_PMP40679_BlankSheet
C38 = CMP-0007049-4: CAP, CERM, 0.047 uF, 50 V, +/- 10%, X7R, 0603; Manufacturer: TDK; TaMin_C: -55°C; ESR_ohm: 0.049007; Polarized: N; SizeAreaWB_mm2: 4.68; Value1: 0.049007 ohm; U/M: EA; TaMax_C: 125°C; SizeZ_mm: 1; SizeX_mm: 1.6; SizeY_mm: 0.8; Value2: 50V; SizeArea_mm2: 1.28; CompType: Capacitor; IRMS_A: 7.67528dA; AEC Category: Q200
J2 = CMP-0002338-1: Header, 100mil, 3x1, Tin, TH; Manufacturer: Sullins Connector Solutions; CNHeader: TRUE; Current_A: 3A; Green_Lifecycle: Not Set; Shrouded: N; Gender: Male; Green_REACh: Incomplete; Voltage_V: 1.8kV; Row_Count: 1; Pitch_mm: 2.54; CT: FALSE; Cert_UL: Y
Logo1 = CMP-0074847-1: FCC_disclaimer; Library Reference: Logo
Logo2 = CMP-0074769-1
Q7 = CMP-0000772-1: MOSFET, N-CH, 60 V, 0.26 A, SOT-23; Alternate Manufacturer: None; Manufacturer: ON Semiconductor; SizeZ_mm: 1.1; ChType: N; Value2: 0.81 nC; VdsMax_V: 60V; SizeX_mm: 2.5; SizeY_mm: 3; Vgs_V: 20V; Value: 60V; SizeArea_mm2: 7.5; AEC Category: Q101; IdsMax_A: 2.6dA; SizeAreaWB_mm2: 14; U/M: EA; QgTyp_nC: 0.81
R22 = CMP-0022735-5: as R9 on sheet PCB_Project_PMP40679_BlankSheet
R23 = CMP-0023152-5: RES, 4.75 k, 1%, 0.1 W, 0603; Manufacturer: Yageo; Power_W: 100mW; TempCo: 100 ppm/C; Value_Code: 4k75; Value: 4.75k; EIA_Code: E96; SizeX_mm: 1.6; SizeY_mm: 0.8; SizeZ_mm: 1; Value2: 0.1W; SizeArea_mm2: 1.28; AEC Qualified: N; VDC_V: 75V; AEC Category: Q200; SizeAreaWB_mm2: 4.68
R24 = CMP-0022892-5: RES, 1.80 k, 1%, 0.1 W, 0603; Manufacturer: Yageo; Power_W: 100mW; TempCo: 100 ppm/C; Value_Code: 1k80; Value: 1.80k; Res_ohm: 1.8k; SizeX_mm: 1.6; SizeY_mm: 0.8; SizeZ_mm: 1; Value2: 0.1W; SizeArea_mm2: 1.28; AEC Qualified: N; VDC_V: 75V; AEC Category: Q200; SizeAreaWB_mm2: 4.68
R25 = CMP-0022763-5: RES, 11.0 k, 1%, 0.1 W, 0603; Manufacturer: Yageo; Power_W: 100mW; TempCo: 100 ppm/C; Value_Code: 11k0; Value: 11.0k; EIA_Code: E96; Res_ohm: 11k; SizeX_mm: 1.6; SizeY_mm: 0.8; SizeZ_mm: 1; Value2: 0.1W; SizeArea_mm2: 1.28; AEC Qualified: N; VDC_V: 75V; AEC Category: Q200; SizeAreaWB_mm2: 4.68
R41 R42 = CMP-0022736-4: as R5 on sheet PCB_Project_PMP40679_BlankSheet
U3 = CMP-0066783-1: 150-mA, 30-V, Ultra-Low IQ, Wide Input Low-Dropout Regulator with Reverse Current Protection, DBV0005A (SOT-23-5); Alternate PartNumber: TPS70950DBVT; Alternate Manufacturer: Texas Instruments; Green_Lifecycle: Active; SizeAreaWB_mm2: 14.82; Green_REACh: Passed; U/M: EA; SizeZ_mm: 1.45; SizeX_mm: 2.8; SizeY_mm: 2.9; SizeArea_mm2: 8.12; CompType: IC
U4 = CMP-0068884-3: CMOS Timer, 8-pin Narrow SOIC; Manufacturer: Texas Instruments; CompType: IC; AEC Category: Q200; AEC Qualified: N; SizeAreaWB_mm2: 56.58; SizeArea_mm2: 30.38; SizeX_mm: 4.9; SizeY_mm: 6.2; SizeZ_mm: 1.75
U5 = CMP-0042683-1: 550 uA/Ch, 3 MHz, Rail-to-Rail Output Operational Amplifier, 2.7 to 16 V, -40 to 125 degC, 5-pin SOT23 (DBV5), Green (RoHS & no Sb/Br); Manufacturer: Texas Instruments; Vio (25C)(Max)(mV): 5; Total Supply Voltage(Min)(+5V is 5, +/-5V is 10): 2.7; Offset Drift(Typ)(uV/C): 2; Rating: Catalog; Number of Channels: 1; Iq per channel(Max)(mA): 0.66; CMRR(Min)(dB): 69; Packing: LARGE T&R; IIB(Max)(pA): 60; Slew Rate(Typ)(V/us): 2.4; GBW(Typ)(MHz): 3; Total Supply Voltage(Max)(+5V is 5, +/-5V is 10): 16; Sub Family: Low Supply Voltage Amplifier (<=2.7V), Precision Amplifier

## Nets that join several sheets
PGND: PCB_Project_PMP40679_BlankSheet (38 pins), PCB_Project_PMP40679_EVM_Hardware (15 pins)
VIN: PCB_Project_PMP40679_BlankSheet (7 pins), PCB_Project_PMP40679_EVM_Hardware (5 pins)
CLK1: PCB_Project_PMP40679_BlankSheet (R5.1), PCB_Project_PMP40679_EVM_Hardware (C33.1 Q7.1 R23.2 U4.3)
CLK2: PCB_Project_PMP40679_BlankSheet (R17.1), PCB_Project_PMP40679_EVM_Hardware (Q7.3 R24.1)
VC: PCB_Project_PMP40679_BlankSheet (R38.2), PCB_Project_PMP40679_EVM_Hardware (C38.2 U5.1)
VIN1: PCB_Project_PMP40679_BlankSheet (7 pins), PCB_Project_PMP40679_EVM_Hardware (R42.1)
VIN2: PCB_Project_PMP40679_BlankSheet (7 pins), PCB_Project_PMP40679_EVM_Hardware (R41.1)

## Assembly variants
001: not fitted FID1 FID2 FID3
